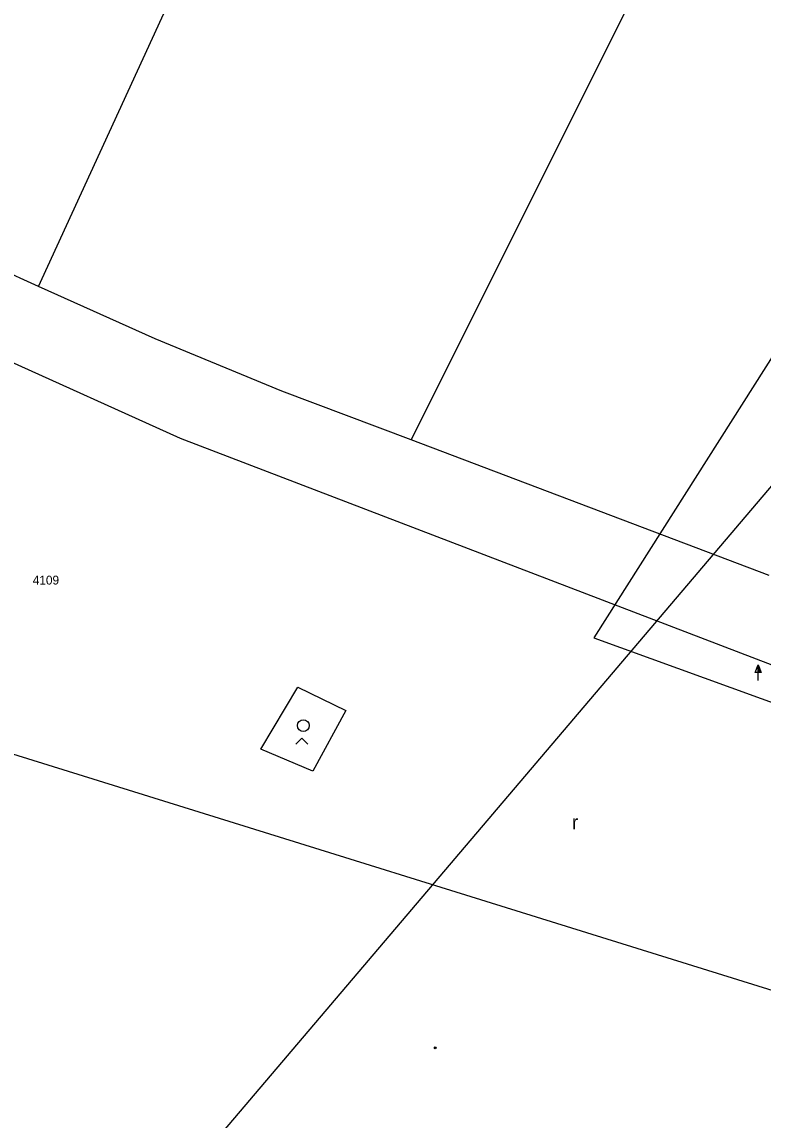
# Model space of a CAD drawing. Extents: x -540150 to -533593, y -1185082 to -1180066.
# Drawn here: x -536148.4 to -536085.7, y -1184689.8 to -1184596.8 of the extents above; entities that cross this region are included whole.
import ezdxf

# ---------------------------------------------------------------- set-up
doc = ezdxf.new("R2010")
doc.units = 0
for name, color, linetype in [('KN_HRAN_PARCEL', 7, 'Continuous'), ('KN_PARC_Č', 7, 'Continuous'), ('maska', 7, 'Continuous'), ('Vrstva 10', 7, 'Continuous'), ('Vrstva 20', 7, 'Continuous'), ('Vrstva 23', 7, 'Continuous'), ('Vrstva 25', 7, 'Continuous'), ('Vrstva 27', 7, 'Continuous'), ('Vrstva 36', 7, 'Continuous')]:
    doc.layers.add(name, color=color, linetype=linetype)

msp = doc.modelspace()

# ---------------------------------------------------------------- linework, layer by layer
at = {"layer": 'KN_HRAN_PARCEL'}
for p, q in [((-536147.031, -1184619.185), (-536116.051, -1184551.765)), ((-536115.491, -1184632.165), (-536082.541, -1184566.365)), ((-536147.031, -1184619.185), (-536177.111, -1184605.665)), ((-536135.001, -1184632.055), (-536165.251, -1184618.435)), ((-536137.151, -1184623.625), (-536147.031, -1184619.185)), ((-536126.441, -1184628.065), (-536137.151, -1184623.625)), ((-536115.491, -1184632.165), (-536126.441, -1184628.065)), ((-536020.911, -1184675.765), (-536135.001, -1184632.055)), ((-536085.171, -1184643.655), (-536115.491, -1184632.165)), ((-536179.721, -1184649.275), (-536017.971, -1184699.595))]:
    msp.add_line(p, q, dxfattribs=at)
at = {"layer": 'maska'}
msp.add_lwpolyline([(-535887.879, -1184642.123), (-535948.538, -1184590.613), (-536025.035, -1184684.958), (-536084.36, -1184635.329), (-536146.543, -1184708.539), (-536168.13, -1184690.208), (-536209.734, -1184739.201)], dxfattribs=at)
at = {"layer": 'Vrstva 10'}
for p, q in [((-536079.302, -1184616.263), (-536100.019, -1184648.932)), ((-536100.019, -1184648.932), (-536068.642, -1184660.317))]:
    msp.add_line(p, q, dxfattribs=at)
at = {"layer": 'Vrstva 20'}
for radius in [0.075, 0.0204]:
    msp.add_circle((-536113.441, -1184683.645), radius, dxfattribs=at)
at = {"layer": 'Vrstva 23'}
for p, q in [((-536128.211, -1184658.355), (-536125.091, -1184653.125)), ((-536125.091, -1184653.125), (-536121.011, -1184655.095)), ((-536121.011, -1184655.095), (-536123.801, -1184660.215)), ((-536123.801, -1184660.215), (-536128.211, -1184658.355))]:
    msp.add_line(p, q, dxfattribs=at)
at = {"layer": 'Vrstva 25'}
for p, q in [((-536086.363, -1184651.883), (-536086.111, -1184651.209)), ((-536086.111, -1184651.883), (-536086.363, -1184651.883)), ((-536086.111, -1184652.535), (-536086.111, -1184651.885))]:
    msp.add_line(p, q, dxfattribs=at)
for points in [[(-536085.861, -1184651.885), (-536086.111, -1184651.885), (-536086.111, -1184651.209), (-536086.111, -1184651.209)], [(-536085.918, -1184651.845), (-536086.071, -1184651.845), (-536086.071, -1184651.432)], [(-536085.976, -1184651.805), (-536086.031, -1184651.805), (-536086.031, -1184651.656)]]:
    msp.add_lwpolyline(points, close=True, dxfattribs=at)
at = {"layer": 'Vrstva 27'}
msp.add_circle((-536124.611, -1184656.365), 0.5, dxfattribs=at)
at = {"layer": 'Vrstva 36'}
msp.add_lwpolyline([(-536125.243, -1184657.943), (-536124.743, -1184657.443), (-536124.243, -1184657.943)], dxfattribs=at)

# ---------------------------------------------------------------- texts
at = {"layer": 'KN_PARC_Č'}
msp.add_text('4109', height=0.75, dxfattribs=at).set_placement((-536147.521, -1184644.425))
at = {"layer": 'Vrstva 36'}
msp.add_text('r', height=1.2, dxfattribs=at).set_placement((-536101.873, -1184665.14))

doc.saveas('drawing.dxf')
